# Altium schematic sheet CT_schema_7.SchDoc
size 287 x 160 mm
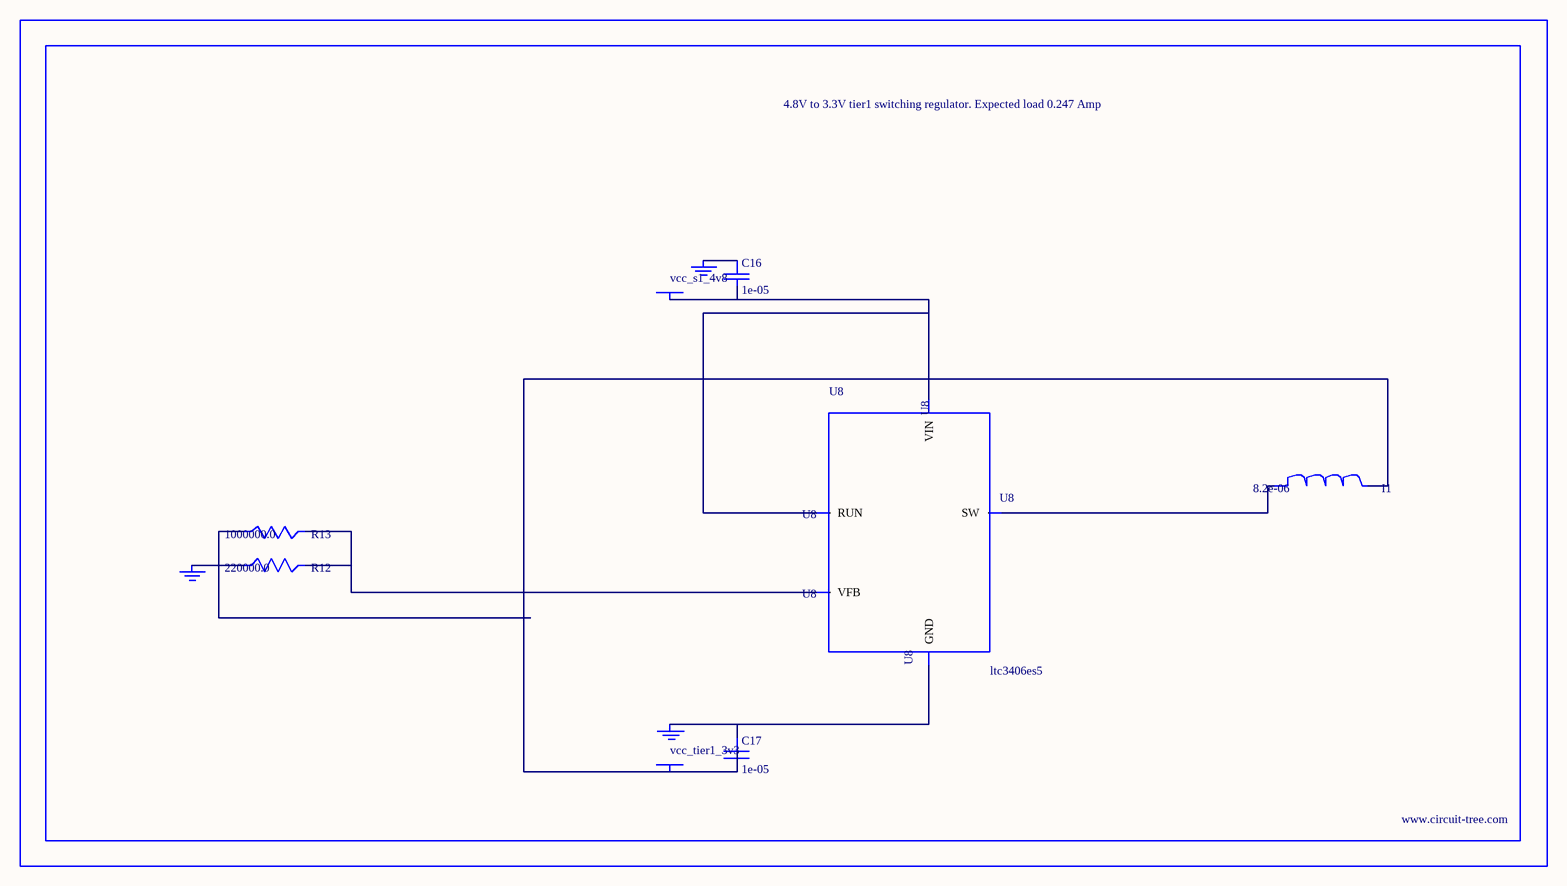
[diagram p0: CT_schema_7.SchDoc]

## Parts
BORDER6  (no value)
C16  1e-05  [C0805]
C17  1e-05  [C0805]
GND_INSTANCE_6_0  (no value)
GND_INSTANCE_6_1  (no value)
GND_INSTANCE_6_2  (no value)
I1  8.2e-06  [DR1040]
POWER_INSTANCE_6_0  vcc_tier1_3v3
POWER_INSTANCE_6_1  vcc_s1_4v8
R12  220000.0  [R0603]
R13  1000000.0  [R0603]
U8  ltc3406es5  [TSOT-23-5]

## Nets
NetC16_1: C16.1 GND_INSTANCE_6_1.0(GND)
NetC16_2: C16.2 POWER_INSTANCE_6_1.0(PWR) U8.1(RUN) U8.4(VIN)
NetC17_1: C17.1 GND_INSTANCE_6_0.0(GND) U8.2(GND)
NetC17_2: C17.2 I1.2 POWER_INSTANCE_6_0.0(PWR) R13.1
NetGND_INSTANCE_6_2_0: GND_INSTANCE_6_2.0(GND) R12.1
NetI1_1: I1.1 U8.3(SW)
NetR12_2: R12.2 R13.2 U8.5(VFB)

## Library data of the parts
BORDER6 = BORDER_PAGE6
C16 C17 = C0805C106K8RACTU
GND_INSTANCE_6_0-GND_INSTANCE_6_2 = GND
I1 = DR1040-8R2-R
POWER_INSTANCE_6_0 POWER_INSTANCE_6_1 = PWR
R12 = RC0603JR-07220KL
R13 = RC0603JR-071ML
